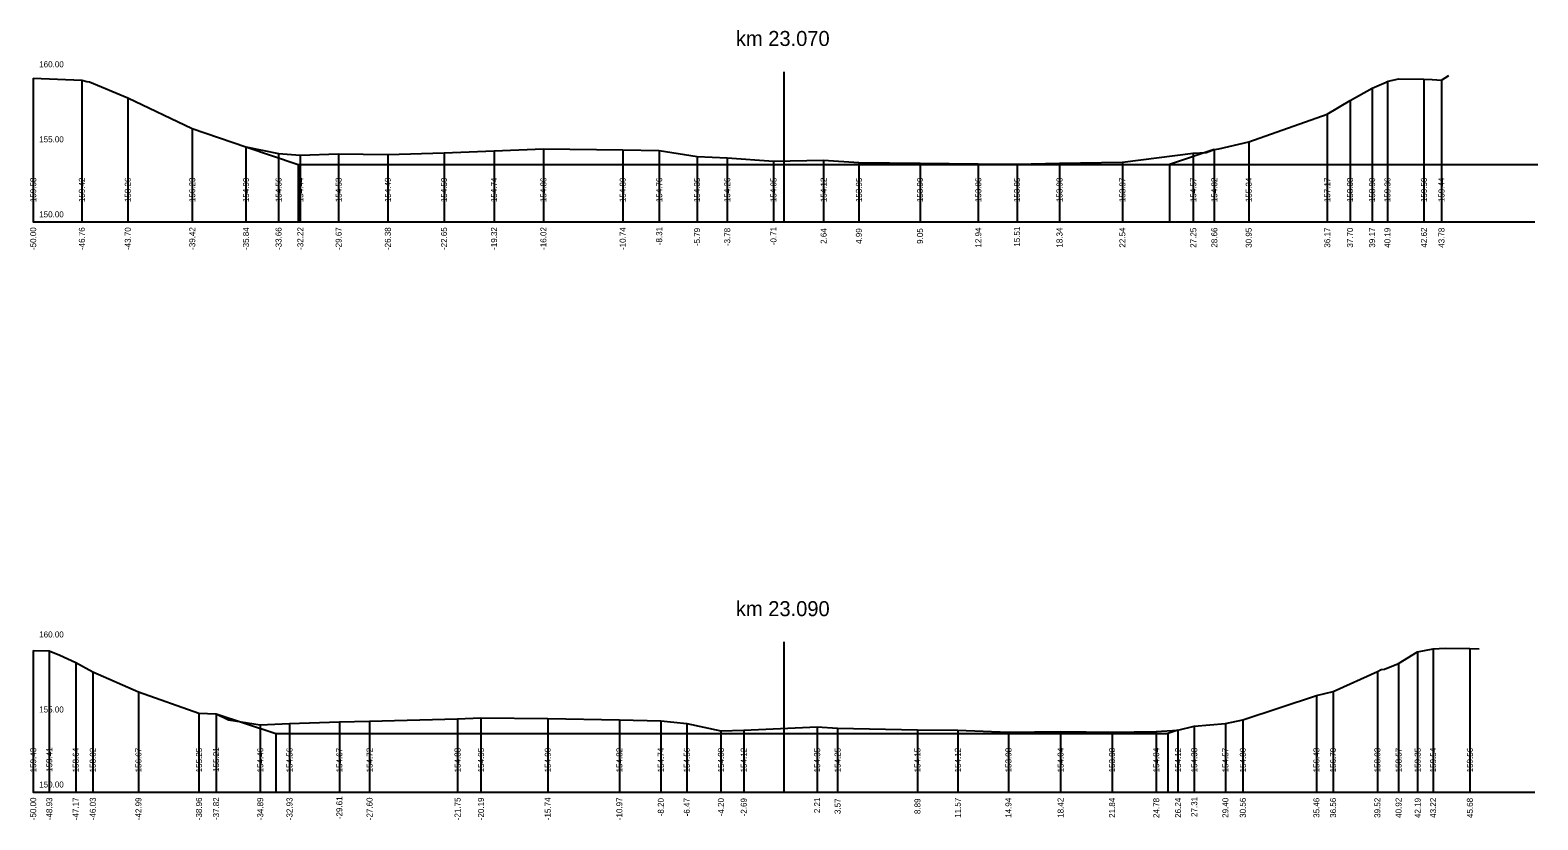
# Model space of a CAD drawing. Extents: x -582678 to -581845, y -1210354 to -1210235.
# Drawn here: x -582055.7 to -581955.2, y -1210306.7 to -1210254.1 of the extents above; entities that cross this region are included whole.
import ezdxf

# ---------------------------------------------------------------- set-up
doc = ezdxf.new("R2010")
doc.units = 0
for name, color, linetype in [('_N_osa', 7, 'Continuous'), ('_N_pomocná', 7, 'Continuous'), ('_N_tučná', 7, 'Continuous'), ('_S_popis', 7, 'Continuous'), ('_S_popis_oprav!', 7, 'Continuous'), ('_S_tenká', 7, 'Continuous'), ('_S_velmi_tenká', 7, 'Continuous')]:
    doc.layers.add(name, color=color, linetype=linetype)

msp = doc.modelspace()

# ---------------------------------------------------------------- linework, layer by layer
at = {"layer": '_N_osa'}
for p, q in [((-582005.45, -1210256.87), (-582005.45, -1210266.87)), ((-582005.45, -1210294.87), (-582005.45, -1210304.87))]:
    msp.add_line(p, q, dxfattribs=at)
at = {"layer": '_N_pomocná'}
for p, q in [((-582037.81, -1210263.04), (-582037.81, -1210266.87)), ((-581979.77, -1210263.04), (-581979.77, -1210266.87)), ((-582039.3, -1210300.98), (-582039.3, -1210304.87)), ((-581979.89, -1210300.98), (-581979.89, -1210304.87))]:
    msp.add_line(p, q, dxfattribs=at)
at = {"layer": '_N_tučná'}
for p, q in [((-582041.28, -1210261.88), (-582037.81, -1210263.04)), ((-581976.79, -1210262.04), (-581979.77, -1210263.04)), ((-582043.27, -1210299.66), (-582039.3, -1210300.98)), ((-581979.21, -1210300.75), (-581979.89, -1210300.98))]:
    msp.add_line(p, q, dxfattribs=at)
for points in [[(-582037.81, -1210263.04), (-581955.24, -1210263.04)], [(-582039.3, -1210300.98), (-581979.89, -1210300.98)]]:
    msp.add_lwpolyline(points, dxfattribs=at)
at = {"layer": '_S_tenká'}
for p, q in [((-582055.45, -1210266.87), (-581955.45, -1210266.87)), ((-582055.45, -1210304.87), (-581955.45, -1210304.87))]:
    msp.add_line(p, q, dxfattribs=at)
for points in [[(-582055.45, -1210257.29), (-582052.21, -1210257.44), (-582051.87, -1210257.51), (-582051.69, -1210257.54), (-582049.15, -1210258.61), (-582044.86, -1210260.64), (-582041.28, -1210261.88), (-582039.11, -1210262.31), (-582037.66, -1210262.43), (-582035.11, -1210262.34), (-582031.83, -1210262.38), (-582028.09, -1210262.28), (-582024.76, -1210262.13), (-582021.47, -1210262.01), (-582016.19, -1210262.07), (-582013.76, -1210262.11), (-582011.24, -1210262.52), (-582009.23, -1210262.61), (-582006.15, -1210262.82), (-582002.81, -1210262.75), (-582000.46, -1210262.91), (-581996.39, -1210262.97), (-581992.51, -1210263), (-581989.93, -1210263.02), (-581987.1, -1210262.97), (-581982.91, -1210262.9), (-581978.19, -1210262.3), (-581977.34, -1210262.24), (-581976.79, -1210262.04), (-581976.49, -1210262.01), (-581974.5, -1210261.53), (-581969.27, -1210259.7), (-581969.27, -1210259.7), (-581969.27, -1210259.7), (-581967.75, -1210258.78), (-581966.28, -1210257.97), (-581965.34, -1210257.56), (-581965.32, -1210257.54), (-581965.26, -1210257.51), (-581965.21, -1210257.5), (-581964.51, -1210257.35), (-581962.83, -1210257.37), (-581962.28, -1210257.39), (-581961.66, -1210257.43), (-581961.17, -1210257.12)], [(-582055.45, -1210295.44), (-582054.38, -1210295.46), (-582053.67, -1210295.75), (-582052.62, -1210296.23), (-582051.48, -1210296.85), (-582048.44, -1210298.2), (-582044.41, -1210299.62), (-582043.27, -1210299.66), (-582042.44, -1210300.06), (-582040.33, -1210300.4), (-582038.38, -1210300.31), (-582035.06, -1210300.2), (-582033.05, -1210300.15), (-582027.19, -1210299.99), (-582025.63, -1210299.92), (-582021.18, -1210299.97), (-582016.41, -1210300.05), (-582013.65, -1210300.13), (-582011.92, -1210300.31), (-582009.65, -1210300.79), (-582008.13, -1210300.75), (-582003.24, -1210300.52), (-582001.88, -1210300.62), (-581996.56, -1210300.72), (-581993.87, -1210300.75), (-581990.5, -1210300.89), (-581987.03, -1210300.83), (-581983.6, -1210300.88), (-581980.66, -1210300.83), (-581979.21, -1210300.75), (-581978.13, -1210300.49), (-581976.05, -1210300.3), (-581974.89, -1210300.07), (-581969.99, -1210298.44), (-581968.88, -1210298.17), (-581965.93, -1210296.84), (-581965.67, -1210296.71), (-581965.46, -1210296.68), (-581964.52, -1210296.3), (-581963.25, -1210295.52), (-581962.8, -1210295.44), (-581962.22, -1210295.33), (-581961.42, -1210295.29), (-581959.77, -1210295.31), (-581959.16, -1210295.33)]]:
    msp.add_lwpolyline(points, dxfattribs=at)
at = {"layer": '_S_velmi_tenká'}
for points in [[(-582055.45, -1210257.29), (-582055.45, -1210266.87), (-582055.45, -1210266.87), (-582055.45, -1210266.87)], [(-582052.21, -1210257.44), (-582052.21, -1210266.87), (-582052.21, -1210266.87), (-582052.21, -1210266.87)], [(-581965.26, -1210257.51), (-581965.26, -1210266.87), (-581965.26, -1210266.87), (-581965.26, -1210266.87)], [(-581962.83, -1210257.37), (-581962.83, -1210266.87), (-581962.83, -1210266.87), (-581962.83, -1210266.87)], [(-581961.66, -1210257.43), (-581961.66, -1210266.87), (-581961.66, -1210266.87), (-581961.66, -1210266.87)], [(-582049.15, -1210258.61), (-582049.15, -1210266.87), (-582049.15, -1210266.87), (-582049.15, -1210266.87)], [(-581967.75, -1210258.78), (-581967.75, -1210266.87), (-581967.75, -1210266.87), (-581967.75, -1210266.87)], [(-581966.28, -1210257.97), (-581966.28, -1210266.87), (-581966.28, -1210266.87), (-581966.28, -1210266.87)], [(-581969.27, -1210259.7), (-581969.27, -1210266.87), (-581969.27, -1210266.87), (-581969.27, -1210266.87)], [(-582044.86, -1210260.64), (-582044.86, -1210266.87), (-582044.86, -1210266.87), (-582044.86, -1210266.87)], [(-582041.28, -1210261.88), (-582041.28, -1210266.87), (-582041.28, -1210266.87), (-582041.28, -1210266.87)], [(-581974.5, -1210261.53), (-581974.5, -1210266.87), (-581974.5, -1210266.87), (-581974.5, -1210266.87)], [(-582039.11, -1210262.31), (-582039.11, -1210266.87), (-582039.11, -1210266.87), (-582039.11, -1210266.87)], [(-582037.66, -1210262.43), (-582037.66, -1210266.87), (-582037.66, -1210266.87), (-582037.66, -1210266.87)], [(-582035.11, -1210262.34), (-582035.11, -1210266.87), (-582035.11, -1210266.87), (-582035.11, -1210266.87)], [(-582031.83, -1210262.38), (-582031.83, -1210266.87), (-582031.83, -1210266.87), (-582031.83, -1210266.87)], [(-582028.09, -1210262.28), (-582028.09, -1210266.87), (-582028.09, -1210266.87), (-582028.09, -1210266.87)], [(-582024.76, -1210262.13), (-582024.76, -1210266.87), (-582024.76, -1210266.87), (-582024.76, -1210266.87)], [(-582021.47, -1210262.01), (-582021.47, -1210266.87), (-582021.47, -1210266.87), (-582021.47, -1210266.87)], [(-582016.19, -1210262.07), (-582016.19, -1210266.87), (-582016.19, -1210266.87), (-582016.19, -1210266.87)], [(-582013.76, -1210262.11), (-582013.76, -1210266.87), (-582013.76, -1210266.87), (-582013.76, -1210266.87)], [(-582011.24, -1210262.52), (-582011.24, -1210266.87), (-582011.24, -1210266.87), (-582011.24, -1210266.87)], [(-582009.23, -1210262.61), (-582009.23, -1210266.87), (-582009.23, -1210266.87), (-582009.23, -1210266.87)], [(-582006.15, -1210262.82), (-582006.15, -1210266.87), (-582006.15, -1210266.87), (-582006.15, -1210266.87)], [(-582002.81, -1210262.75), (-582002.81, -1210266.87), (-582002.81, -1210266.87), (-582002.81, -1210266.87)], [(-582000.46, -1210262.91), (-582000.46, -1210266.87), (-582000.46, -1210266.87), (-582000.46, -1210266.87)], [(-581987.1, -1210262.97), (-581987.1, -1210266.87), (-581987.1, -1210266.87), (-581987.1, -1210266.87)], [(-581982.91, -1210262.9), (-581982.91, -1210266.87), (-581982.91, -1210266.87), (-581982.91, -1210266.87)], [(-581978.19, -1210262.3), (-581978.19, -1210266.87), (-581978.19, -1210266.87), (-581978.19, -1210266.87)], [(-581976.79, -1210262.04), (-581976.79, -1210266.87), (-581976.79, -1210266.87), (-581976.79, -1210266.87)], [(-581996.39, -1210262.97), (-581996.39, -1210266.87), (-581996.39, -1210266.87), (-581996.39, -1210266.87)], [(-581992.51, -1210263), (-581992.51, -1210266.87), (-581992.51, -1210266.87), (-581992.51, -1210266.87)], [(-581989.93, -1210263.02), (-581989.93, -1210266.87), (-581989.93, -1210266.87), (-581989.93, -1210266.87)], [(-582055.45, -1210295.44), (-582055.45, -1210304.87), (-582055.45, -1210304.87), (-582055.45, -1210304.87)], [(-582054.38, -1210295.46), (-582054.38, -1210304.87), (-582054.38, -1210304.87), (-582054.38, -1210304.87)], [(-581963.25, -1210295.52), (-581963.25, -1210304.87), (-581963.25, -1210304.87), (-581963.25, -1210304.87)], [(-581962.22, -1210295.33), (-581962.22, -1210304.87), (-581962.22, -1210304.87), (-581962.22, -1210304.87)], [(-581959.77, -1210295.31), (-581959.77, -1210304.87), (-581959.77, -1210304.87), (-581959.77, -1210304.87)], [(-582052.62, -1210296.23), (-582052.62, -1210304.87), (-582052.62, -1210304.87), (-582052.62, -1210304.87)], [(-582051.48, -1210296.85), (-582051.48, -1210304.87), (-582051.48, -1210304.87), (-582051.48, -1210304.87)], [(-581965.93, -1210296.84), (-581965.93, -1210304.87), (-581965.93, -1210304.87), (-581965.93, -1210304.87)], [(-581964.52, -1210296.3), (-581964.52, -1210304.87), (-581964.52, -1210304.87), (-581964.52, -1210304.87)], [(-582048.44, -1210298.2), (-582048.44, -1210304.87), (-582048.44, -1210304.87), (-582048.44, -1210304.87)], [(-581969.99, -1210298.44), (-581969.99, -1210304.87), (-581969.99, -1210304.87), (-581969.99, -1210304.87)], [(-581968.88, -1210298.17), (-581968.88, -1210304.87), (-581968.88, -1210304.87), (-581968.88, -1210304.87)], [(-582044.41, -1210299.62), (-582044.41, -1210304.87), (-582044.41, -1210304.87), (-582044.41, -1210304.87)], [(-582043.27, -1210299.66), (-582043.27, -1210304.87), (-582043.27, -1210304.87), (-582043.27, -1210304.87)], [(-582027.19, -1210299.99), (-582027.19, -1210304.87), (-582027.19, -1210304.87), (-582027.19, -1210304.87)], [(-582025.63, -1210299.92), (-582025.63, -1210304.87), (-582025.63, -1210304.87), (-582025.63, -1210304.87)], [(-582021.18, -1210299.97), (-582021.18, -1210304.87), (-582021.18, -1210304.87), (-582021.18, -1210304.87)], [(-582016.41, -1210300.05), (-582016.41, -1210304.87), (-582016.41, -1210304.87), (-582016.41, -1210304.87)], [(-581974.89, -1210300.07), (-581974.89, -1210304.87), (-581974.89, -1210304.87), (-581974.89, -1210304.87)], [(-582040.33, -1210300.4), (-582040.33, -1210304.87), (-582040.33, -1210304.87), (-582040.33, -1210304.87)], [(-582038.38, -1210300.31), (-582038.38, -1210304.87), (-582038.38, -1210304.87), (-582038.38, -1210304.87)], [(-582035.06, -1210300.2), (-582035.06, -1210304.87), (-582035.06, -1210304.87), (-582035.06, -1210304.87)], [(-582033.05, -1210300.15), (-582033.05, -1210304.87), (-582033.05, -1210304.87), (-582033.05, -1210304.87)], [(-582013.65, -1210300.13), (-582013.65, -1210304.87), (-582013.65, -1210304.87), (-582013.65, -1210304.87)], [(-582011.92, -1210300.31), (-582011.92, -1210304.87), (-582011.92, -1210304.87), (-582011.92, -1210304.87)], [(-582009.65, -1210300.79), (-582009.65, -1210304.87), (-582009.65, -1210304.87), (-582009.65, -1210304.87)], [(-582008.13, -1210300.75), (-582008.13, -1210304.87), (-582008.13, -1210304.87), (-582008.13, -1210304.87)], [(-582003.24, -1210300.52), (-582003.24, -1210304.87), (-582003.24, -1210304.87), (-582003.24, -1210304.87)], [(-582001.88, -1210300.62), (-582001.88, -1210304.87), (-582001.88, -1210304.87), (-582001.88, -1210304.87)], [(-581996.56, -1210300.72), (-581996.56, -1210304.87), (-581996.56, -1210304.87), (-581996.56, -1210304.87)], [(-581993.87, -1210300.75), (-581993.87, -1210304.87), (-581993.87, -1210304.87), (-581993.87, -1210304.87)], [(-581990.5, -1210300.89), (-581990.5, -1210304.87), (-581990.5, -1210304.87), (-581990.5, -1210304.87)], [(-581987.03, -1210300.83), (-581987.03, -1210304.87), (-581987.03, -1210304.87), (-581987.03, -1210304.87)], [(-581983.6, -1210300.88), (-581983.6, -1210304.87), (-581983.6, -1210304.87), (-581983.6, -1210304.87)], [(-581980.66, -1210300.83), (-581980.66, -1210304.87), (-581980.66, -1210304.87), (-581980.66, -1210304.87)], [(-581979.21, -1210300.75), (-581979.21, -1210304.87), (-581979.21, -1210304.87), (-581979.21, -1210304.87)], [(-581978.13, -1210300.49), (-581978.13, -1210304.87), (-581978.13, -1210304.87), (-581978.13, -1210304.87)], [(-581976.05, -1210300.3), (-581976.05, -1210304.87), (-581976.05, -1210304.87), (-581976.05, -1210304.87)]]:
    msp.add_lwpolyline(points, dxfattribs=at)

# ---------------------------------------------------------------- texts
at = {"layer": '_S_popis'}
for s, p in [('160.00', (-582055.05, -1210256.57)), ('155.00', (-582055.05, -1210261.57)), ('150.00', (-582055.05, -1210266.57)), ('160.00', (-582055.05, -1210294.57)), ('155.00', (-582055.05, -1210299.57)), ('150.00', (-582055.05, -1210304.57))]:
    msp.add_text(s, height=0.4, dxfattribs=at).set_placement(p)
for s, p in [('159.58', (-582055.25, -1210265.56)), ('159.42', (-582052.01, -1210265.56)), ('158.26', (-582048.95, -1210265.56)), ('156.23', (-582044.66, -1210265.56)), ('154.99', (-582041.08, -1210265.56)), ('154.56', (-582038.91, -1210265.56)), ('154.44', (-582037.46, -1210265.56)), ('154.53', (-582034.91, -1210265.56)), ('154.49', (-582031.63, -1210265.56)), ('154.59', (-582027.89, -1210265.56)), ('154.74', (-582024.56, -1210265.56)), ('154.86', (-582021.27, -1210265.56)), ('154.80', (-582015.99, -1210265.56)), ('154.76', (-582013.56, -1210265.56)), ('154.35', (-582011.04, -1210265.56)), ('154.26', (-582009.03, -1210265.56)), ('154.05', (-582005.95, -1210265.56)), ('154.12', (-582002.61, -1210265.56)), ('153.95', (-582000.26, -1210265.56)), ('153.90', (-581996.19, -1210265.56)), ('153.86', (-581992.31, -1210265.56)), ('153.85', (-581989.73, -1210265.56)), ('153.90', (-581986.9, -1210265.56)), ('153.97', (-581982.71, -1210265.56)), ('154.57', (-581977.99, -1210265.56)), ('154.82', (-581976.59, -1210265.56)), ('155.34', (-581974.3, -1210265.56)), ('157.17', (-581969.07, -1210265.56)), ('158.08', (-581967.55, -1210265.56)), ('158.90', (-581966.08, -1210265.56)), ('159.36', (-581965.06, -1210265.56)), ('159.50', (-581962.63, -1210265.56)), ('159.44', (-581961.46, -1210265.56)), ('-50.00', (-582055.25, -1210268.75)), ('-46.76', (-582052.01, -1210268.75)), ('-43.70', (-582048.95, -1210268.75)), ('-39.42', (-582044.66, -1210268.74)), ('-35.84', (-582041.08, -1210268.75)), ('-33.66', (-582038.91, -1210268.75)), ('-32.22', (-582037.46, -1210268.74)), ('-29.67', (-582034.91, -1210268.75)), ('-26.38', (-582031.63, -1210268.75)), ('-22.65', (-582027.89, -1210268.75)), ('-19.32', (-582024.56, -1210268.74)), ('-16.02', (-582021.27, -1210268.74)), ('-10.74', (-582015.99, -1210268.75)), ('-8.31', (-582013.56, -1210268.43)), ('-5.79', (-582011.04, -1210268.49)), ('-3.78', (-582009.03, -1210268.49)), ('-0.71', (-582005.95, -1210268.43)), ('2.64', (-582002.61, -1210268.34)), ('4.99', (-582000.26, -1210268.34)), ('9.05', (-581996.19, -1210268.34)), ('12.94', (-581992.31, -1210268.59)), ('15.51', (-581989.73, -1210268.53)), ('18.34', (-581986.9, -1210268.59)), ('22.54', (-581982.71, -1210268.59)), ('27.25', (-581977.99, -1210268.6)), ('28.66', (-581976.59, -1210268.59)), ('30.95', (-581974.3, -1210268.6)), ('36.17', (-581969.07, -1210268.59)), ('37.70', (-581967.55, -1210268.59)), ('39.17', (-581966.08, -1210268.59)), ('40.19', (-581965.06, -1210268.6)), ('42.62', (-581962.63, -1210268.59)), ('43.78', (-581961.46, -1210268.6)), ('159.43', (-582055.25, -1210303.56)), ('159.41', (-582054.18, -1210303.53)), ('158.64', (-582052.42, -1210303.56)), ('158.02', (-582051.28, -1210303.56)), ('156.67', (-582048.24, -1210303.56)), ('155.25', (-582044.21, -1210303.56)), ('155.21', (-582043.07, -1210303.53)), ('154.46', (-582040.13, -1210303.56)), ('154.56', (-582038.18, -1210303.56)), ('154.67', (-582034.86, -1210303.56)), ('154.72', (-582032.85, -1210303.56)), ('154.88', (-582026.99, -1210303.56)), ('154.95', (-582025.43, -1210303.56)), ('154.90', (-582020.98, -1210303.56)), ('154.82', (-582016.21, -1210303.56)), ('154.74', (-582013.45, -1210303.56)), ('154.56', (-582011.72, -1210303.56)), ('154.08', (-582009.45, -1210303.56)), ('154.12', (-582007.93, -1210303.56)), ('154.35', (-582003.04, -1210303.56)), ('154.25', (-582001.68, -1210303.56)), ('154.15', (-581996.36, -1210303.56)), ('154.12', (-581993.67, -1210303.56)), ('153.98', (-581990.3, -1210303.56)), ('154.04', (-581986.83, -1210303.56)), ('153.98', (-581983.4, -1210303.56)), ('154.04', (-581980.46, -1210303.56)), ('154.12', (-581979.01, -1210303.56)), ('154.38', (-581977.93, -1210303.56)), ('154.57', (-581975.85, -1210303.56)), ('154.80', (-581974.69, -1210303.56)), ('156.43', (-581969.79, -1210303.56)), ('156.70', (-581968.68, -1210303.56)), ('158.03', (-581965.73, -1210303.56)), ('158.57', (-581964.32, -1210303.56)), ('159.35', (-581963.05, -1210303.56)), ('159.54', (-581962.02, -1210303.56)), ('159.56', (-581959.57, -1210303.56)), ('-50.00', (-582055.25, -1210306.75)), ('-48.93', (-582054.18, -1210306.75)), ('-47.17', (-582052.42, -1210306.75)), ('-46.03', (-582051.28, -1210306.75)), ('-42.99', (-582048.24, -1210306.75)), ('-38.96', (-582044.21, -1210306.75)), ('-37.82', (-582043.07, -1210306.74)), ('-34.89', (-582040.13, -1210306.75)), ('-32.93', (-582038.18, -1210306.75)), ('-29.61', (-582034.86, -1210306.68)), ('-27.60', (-582032.85, -1210306.75)), ('-21.75', (-582026.99, -1210306.75)), ('-20.19', (-582025.43, -1210306.75)), ('-15.74', (-582020.98, -1210306.75)), ('-10.97', (-582016.21, -1210306.75)), ('-8.20', (-582013.45, -1210306.49)), ('-6.47', (-582011.72, -1210306.49)), ('-4.20', (-582009.45, -1210306.49)), ('-2.69', (-582007.93, -1210306.49)), ('2.21', (-582003.04, -1210306.28)), ('3.57', (-582001.68, -1210306.34)), ('8.89', (-581996.36, -1210306.34)), ('11.57', (-581993.67, -1210306.59)), ('14.94', (-581990.3, -1210306.59)), ('18.42', (-581986.83, -1210306.59)), ('21.84', (-581983.4, -1210306.59)), ('24.78', (-581980.46, -1210306.6)), ('26.24', (-581979.01, -1210306.59)), ('27.31', (-581977.93, -1210306.53)), ('29.40', (-581975.85, -1210306.59)), ('30.56', (-581974.69, -1210306.59)), ('35.46', (-581969.79, -1210306.59)), ('36.56', (-581968.68, -1210306.59)), ('39.52', (-581965.73, -1210306.59)), ('40.92', (-581964.32, -1210306.59)), ('42.19', (-581963.05, -1210306.6)), ('43.22', (-581962.02, -1210306.59)), ('45.68', (-581959.57, -1210306.6))]:
    msp.add_text(s, height=0.4, rotation=90, dxfattribs=at).set_placement(p)
at = {"layer": '_S_popis_oprav!'}
for s, p in [('km 23.070', (-582008.65, -1210255.15)), ('km 23.090', (-582008.65, -1210293.15))]:
    msp.add_text(s, height=1, dxfattribs=at).set_placement(p)

doc.saveas('drawing.dxf')
